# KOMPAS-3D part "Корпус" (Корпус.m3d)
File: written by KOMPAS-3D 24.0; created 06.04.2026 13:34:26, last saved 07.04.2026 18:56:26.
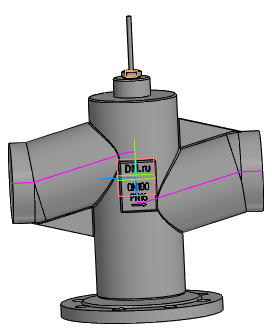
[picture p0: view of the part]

Document properties: Автор: R2D2; Полное имя файла: E:\Работа\Зайцев\Солянка\VSR1-13V-PED-F Клапан запорно-регулирующий DN.ru\DN100\исходные материалы\Корпус.m3d

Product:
- Body: Труба / Нестандартная труба / L = 174.6 мм  | qty 1
    Материал: Нестандартная труба (density 7856 kg/m3)
    Масса: 43.000119
    Раздел спецификации: Детали
    Примечание: 13,03 кг
    additional columns: Pipeline; 0.11; 0; 0; 0.002; 0.17456; true; 0.04
- Body: Труба / Нестандартная труба / L = 174.6 мм  | qty 1
    Материал: Нестандартная труба (density 7856 kg/m3)
    Масса: 43.000119
    Раздел спецификации: Детали
    Форматы листов документа: БЧ
    Примечание: 13,03 кг
    additional columns: Pipeline; 0.11; 0; 0; 0.002; 0.17456; true; 0.04
- Component [standard]: Гайка М16-6H ГОСТ 5916-70  | qty 1  | Масса: 0.01768; Рассекать на разрезах: no; source file: C:\Program Files\ASCON\KOMPAS-3D v24\Libs\PolynomLib\DATA\vault\Methods\Kompas\3D\PLib_Nut_OST92_900.m3d
- Component [standard]: (unnamed)  | qty 1  | Материал: ВЧ40 ГОСТ 7293-85 (density 7200 kg/m3); Масса: 4.843341; Рассекать на разрезах: no; additional columns: 100-16-B-2-ВЧ40-II; Заглушка; ГОСТ 34785-2021
- Body: Тело 4  | qty 1
    Материал: Нестандартная труба (density 7856 kg/m3)
    Масса: 43.000119
- Part/product: Корпус
    Масса: 6.9

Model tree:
1. Эскиз:1
2. Труба:1  (labels: {F703FF30-5BE6-4673-A7F1-8EDA1BE1E2D1}; SHAPEOBJECT3D_ATTR_BUTT; SHAPEOBJECT3D_ATTR_VALID; SHAPEOBJECT3D_ATTR_BUTT_AREA)
     PIPE_R = 7
3. Труба:2  (labels: {F703FF30-5BE6-4673-A7F1-8EDA1BE1E2D1}; SHAPEOBJECT3D_ATTR_BUTT; SHAPEOBJECT3D_ATTR_VALID; SHAPEOBJECT3D_ATTR_BUTT_AREA)
     PIPE_R = 7
4. Эскиз:2
5. Элемент выдавливания:1
     Расстояние 1 = 137; Смещение 1 = -1; Расстояние 2 = 161; Смещение 2 = -5
6. РЕБРО  (with: Ребро.Труба:1, Грань.Элемент выдавливания:1, Грань.Труба:1, Грань.Труба:2)
7. Элемент выдавливания:2
     Расстояние 1 = 6
8. Эскиз:4  (with: Грань.Элемент выдавливания:1)
9. Скругление:3  (with: Ребро.Элемент выдавливания:2)
10. Элемент выдавливания:3
     Расстояние 1 = 1
11. Эскиз:5  (with: Грань.Элемент выдавливания:3)
12. Элемент выдавливания:4
     Расстояние 1 = 7.5; Смещение 1 = 0.5
13. ШТОК
14. Элемент выдавливания:5
15. ОТЛИВКА
16. Скругление:6  (with: Грань.Элемент выдавливания:1)
17. Элемент выдавливания:6  (with: Грань.Элемент выдавливания:1)
     Смещение 1 = 4
18. ТЕКСТ  (with: Грань.Элемент выдавливания:6)
19. Элемент выдавливания:7
     Расстояние 1 = 0.5
20. Скругление:7  (with: Ребро.Элемент выдавливания:6)
     Радиус = 2
21. Эскиз:9  (with: Грань.Элемент выдавливания:1, Ребро.Скругление:6, Ребро.Элемент выдавливания:5)
22. Элемент вращения:1
     Угол 1 = 360
23. Скругление:8  (with: Ребро.Элемент вращения:1, Грань.Элемент выдавливания:3)
     Радиус = 2

Expressions: DS/2+3; v22*2
Referenced files in C:\Program Files\ASCON\KOMPAS-3D v24\Libs\Pipeline\: StylesTemplate.a3d, TemplateHPH, InsulationStylesTemplate.a3d, Insulation
Referenced files in C:\Program Files\ASCON\KOMPAS-3D v24\Templates\: Констр. чертеж А3 гориз. перв. лист.cdt
Referenced files in E:\Работа\Зайцев\Солянка\VSR1-13V-PED-F Клапан запорно-регулирующий DN.ru\DN15\DN15 Kv0.16\исходные материалы\: 
Referenced files in C:\Program Files\ASCON\KOMPAS-3D v24\Libs\PolynomLib\DATA\vault\Methods\Kompas\3D\: PLib_Nut_OST92_900.m3d, PLib_Flange_Blind_GOST_34785_2100.m3d
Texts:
  Отводы ГОСТ 17375-2001
  Констр. чертеж А3 гориз. перв. лист.cdt
  BOSimple***PART:2c8e7818-1586-f79e-db7d-bc045ba468e4***SHORTLOC:Root±30±10±20±©{}110±10±50±80[Нет;Без покрытия;Без указания материала;-;16;2;24]
  BOSimple***Material:38d6725a-5efe-48e1-b177-a7817acb862a
  BOSimple***PART:fb787e56-456e-79e6-e20d-f7f134aa128e***SHORTLOC:B619_EF039B503CC34112[2;16;100;Круглая;II;ВЧ40 ГОСТ 7293-85]
  var3D
  PN16
  LL-10
  DN+10
  bcut1
  hole1
  hcut1
  hole2
  cut1
  Труба / Нестандартная труба / L = %s мм
  Plane. Начало координат
  Ось Y.Начало координат
  Плоскость ZX.Начало координат
  Горизонтальная плоскость. Начало координат
  Плоскость XY.Начало координат
  Плоскость ZY.Начало координат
